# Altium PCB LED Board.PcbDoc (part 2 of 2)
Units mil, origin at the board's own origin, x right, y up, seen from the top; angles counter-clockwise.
Board outline 11968.5 x 3779.53 mil, 2 copper layers (Top Layer, Bottom Layer); 272 components, 796 nets, 779 pads, 57 vias.
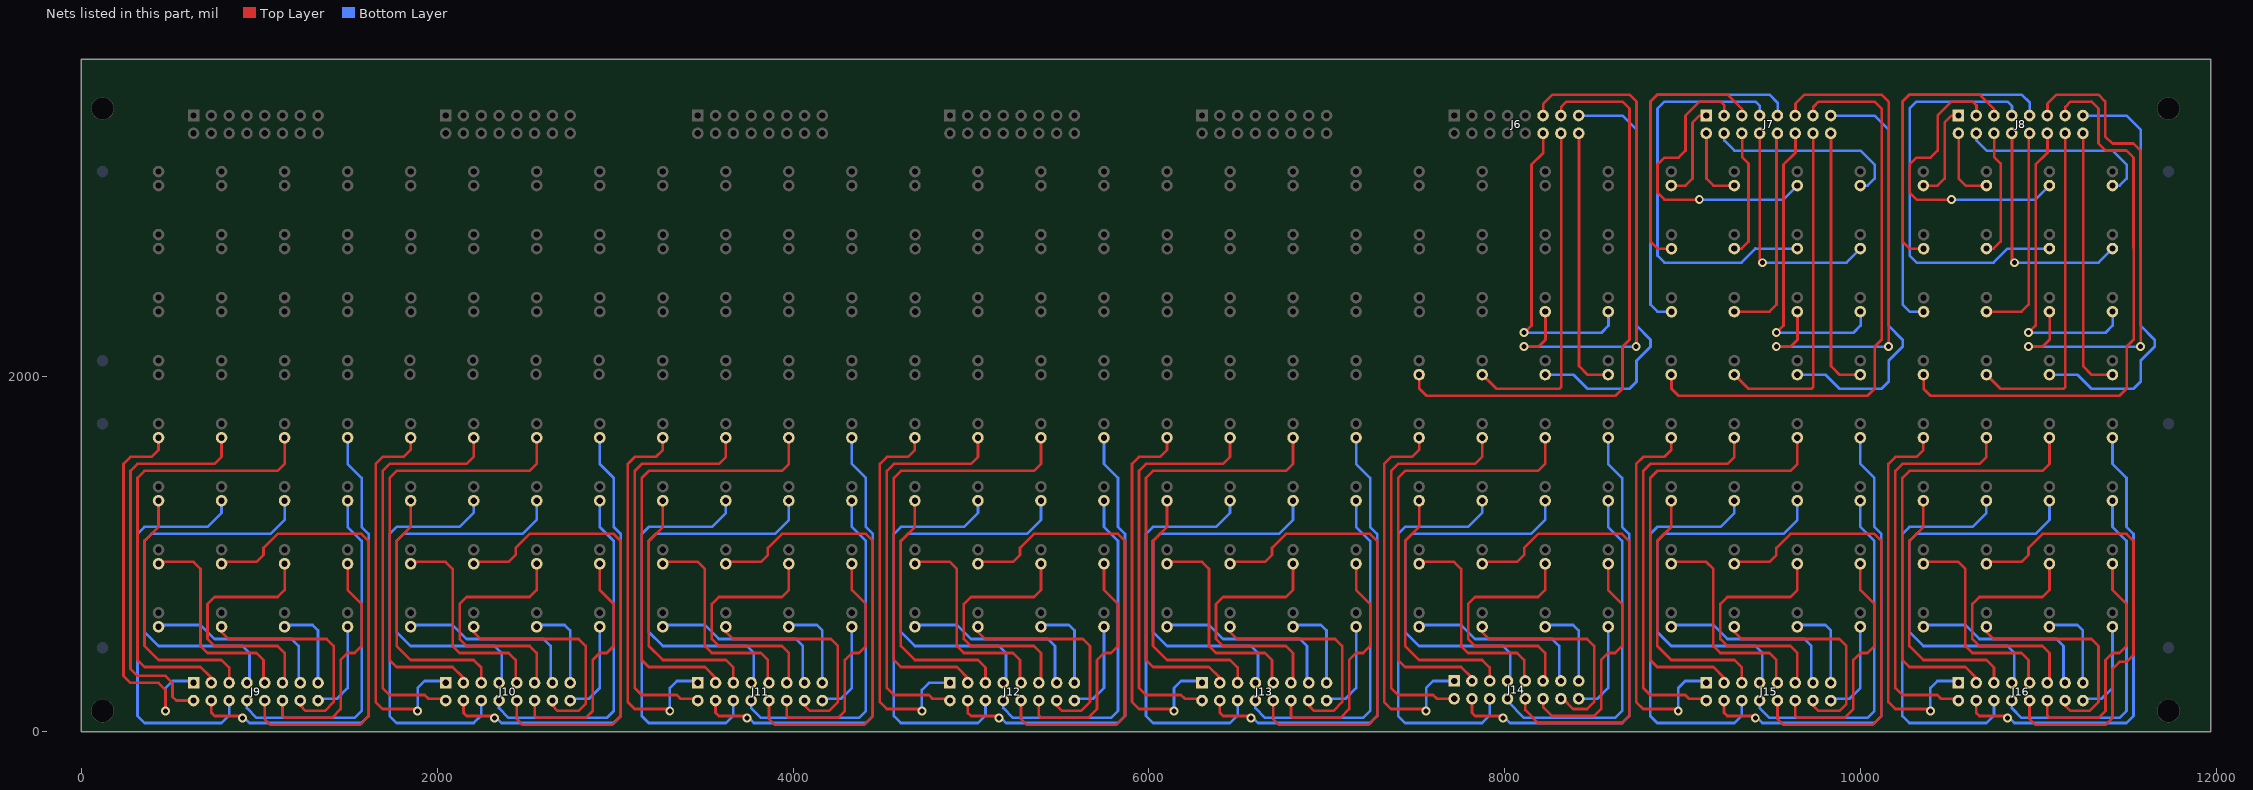
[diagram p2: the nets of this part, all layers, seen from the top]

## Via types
v1: diameter 50, hole 28, Top Layer to Bottom Layer, 57 vias

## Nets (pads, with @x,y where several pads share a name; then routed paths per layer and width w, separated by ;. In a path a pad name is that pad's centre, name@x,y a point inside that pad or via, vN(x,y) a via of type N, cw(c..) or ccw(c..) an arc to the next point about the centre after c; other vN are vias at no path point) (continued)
A91: D91.2 J6.11 | length 2927.8
  Top Layer w15: v1@8111.65,2164.72 8190.39,2164.72 8229.76,2204.09 D91.2@8229.76,2361.57 ; J6.11@8217.95,3463.94 8217.95,3530.86 8269.13,3582.05 8702.2,3582.05 8741.57,3542.68 v1@8741.57,2164.72
  Bottom Layer w15: v1@8111.65,2164.72 v1@8741.57,2164.72
  other v1: 8110.24,2165.35 8740.16,2165.35
A92: D92.2 J6.12 | length 1732
  Top Layer w15: v1@8111.65,2243.46 8151.02,2282.83 8151.02,3188.35 8217.95,3255.27 J6.12@8217.95,3363.94
  Bottom Layer w15: v1@8111.65,2243.46 8544.72,2243.46 8584.09,2282.83 D92.2@8584.09,2361.57
  other v1: 8110.24,2244.09
A93: D93.2 J6.13 | length 3306
  Top Layer w15: D93.2@7521.1,2007.24 7521.1,1928.5 7560.47,1889.13 8623.46,1889.13 8662.83,1928.5 8662.83,2164.72 8702.2,2204.09 8702.2,3503.31 8662.83,3542.68 8347.87,3542.68 8317.95,3512.75 J6.13@8317.95,3463.94
A94: D94.2 J6.14 | length 1905
  Top Layer w15: D94.2@7875.43,2007.24 7954.17,1928.5 8308.5,1928.5 8317.95,1937.95 J6.14@8317.95,3363.94
A95: D95.2 J6.15 | length 2399.5
  Bottom Layer w15: D95.2@8229.76,2007.24 8387.24,2007.24 8465.98,1928.5 8702.2,1928.5 8741.57,1967.87 8741.57,2085.98 8820.31,2164.72 8820.31,2204.09 8741.57,2282.83 8741.57,3385.2 8662.83,3463.94 J6.15@8417.95,3463.94
A96: D96.2 J6.16 | length 1494.7
  Top Layer w15: J6.16@8417.95,3363.94 8417.95,2055.28 8465.98,2007.24 D96.2@8584.09,2007.24
A97: D97.2 J7.1 | length 544.4
  Top Layer w15: D97.2@8938.42,3070.24 9017.17,3070.24 9056.54,3109.61 9056.54,3424.57 9095.9,3463.94 J7.1@9135.27,3463.94
A98: D98.2 J7.2 | length 428.1
  Top Layer w15: J7.2@9135.27,3363.94 9135.27,3109.61 9174.65,3070.24 D98.2@9292.76,3070.24
A99: D99.2 J7.3 | length 1697.8
  Top Layer w15: v1@9095.91,2991.5 8899.06,2991.5 8859.68,3030.87 8859.68,3188.35 8899.06,3227.72 8977.8,3227.72 9017.17,3267.09 9017.17,3463.94 9095.91,3542.68 9214.02,3542.68 9235.27,3521.42 J7.3@9235.27,3463.94
  Bottom Layer w15: v1@9095.91,2991.5 9568.35,2991.5 D99.2@9647.09,3070.24
  other v1: 9094.49,2992.13
A100: D100.2 J7.4 | length 1114.5
  Bottom Layer w15: J7.4@9235.27,3363.94 9235.27,3324.57 9292.76,3267.09 10001.42,3267.09 10080.16,3188.35 10080.16,3109.61 10040.79,3070.24 D100.2@10001.42,3070.24
A101: D101.2 J7.5 | length 1523.2
  Top Layer w15: D101.2@8938.43,2715.91 8859.69,2715.91 8820.31,2755.28 8820.31,3542.68 8859.68,3582.05 9253.39,3582.05 9335.27,3500.16 J7.5@9335.27,3463.94
A102: D102.2 J7.6 | length 718.7
  Top Layer w15: D102.2@9292.76,2715.91 9332.13,2715.91 9371.5,2755.28 9371.5,3194.64 9335.27,3230.86 J7.6@9335.27,3363.94
A103: D103.2 J7.7 | length 2319.4
  Bottom Layer w15: 9330.71,2637.8 9409.45,2716.54 ; 9332.13,2637.17 8899.06,2637.17 8859.68,2676.54 8859.68,3503.31 8899.06,3542.68 9410.87,3542.68 9435.27,3518.27 J7.7@9435.27,3463.94 ; 9410.87,2715.91 D103.2@9647.09,2715.91
A104: D104.2 J7.8 | length 1316.8
  Top Layer w15: J7.8@9435.27,3363.94 9435.27,2652.13 v1(9450.24,2637.17)
  Bottom Layer w15: v1(9450.24,2637.17) 9922.68,2637.17 D104.2@10001.42,2715.91
A105: D105.2 J7.9 | length 2098.8
  Bottom Layer w15: D105.2@8938.42,2361.58 8859.68,2361.57 8820.32,2400.94 8820.32,3542.68 8859.68,3582.05 9489.61,3582.05 9535.27,3536.38 J7.9@9535.27,3463.94
A106: D106.2 J7.10 | length 1218.1
  Top Layer w15: D106.2@9292.76,2361.57 9489.61,2361.57 9528.98,2400.94 9528.98,3357.64 J7.10@9535.27,3363.94
A107: D107.2 J7.11 | length 2927.8
  Top Layer w15: v1@9528.98,2164.72 9607.72,2164.72 9647.09,2204.09 D107.2@9647.09,2361.57 ; J7.11@9635.27,3463.94 9635.27,3530.86 9686.46,3582.05 10119.53,3582.05 10158.9,3542.68 v1@10158.9,2164.72
  Bottom Layer w15: v1@9528.98,2164.72 v1@10158.9,2164.72
  other v1: 9527.56,2165.35 10157.48,2165.35
A108: D108.2 J7.12 | length 1732
  Top Layer w15: v1@9528.98,2243.46 9568.35,2282.83 9568.35,3188.35 9635.27,3255.27 J7.12@9635.27,3363.94
  Bottom Layer w15: v1@9528.98,2243.46 9962.05,2243.46 10001.42,2282.83 D108.2@10001.42,2361.57
  other v1: 9527.56,2244.09
A109: D109.2 J7.13 | length 3306
  Top Layer w15: D109.2@8938.43,2007.24 8938.43,1928.5 8977.8,1889.13 10040.79,1889.13 10080.16,1928.5 10080.16,2164.72 10119.53,2204.09 10119.53,3503.31 10080.16,3542.68 9765.2,3542.68 9735.27,3512.75 J7.13@9735.27,3463.94
A110: D110.2 J7.14 | length 1905
  Top Layer w15: D110.2@9292.76,2007.24 9371.5,1928.5 9725.83,1928.5 9735.27,1937.95 J7.14@9735.27,3363.94
A111: D111.2 J7.15 | length 2399.5
  Bottom Layer w15: D111.2@9647.09,2007.24 9804.57,2007.24 9883.31,1928.5 10119.53,1928.5 10158.9,1967.87 10158.9,2085.98 10237.64,2164.72 10237.64,2204.09 10158.9,2282.83 10158.9,3385.2 10080.16,3463.94 J7.15@9835.27,3463.94
A112: D112.2 J7.16 | length 1494.7
  Top Layer w15: J7.16@9835.27,3363.94 9835.27,2055.28 9883.31,2007.24 D112.2@10001.42,2007.24
A113: D113.2 J8.1 | length 544.4
  Top Layer w15: D113.2@10355.75,3070.24 10434.49,3070.24 10473.86,3109.61 10473.86,3424.57 10513.23,3463.94 J8.1@10552.6,3463.94
A114: D114.2 J8.2 | length 428.1
  Top Layer w15: J8.2@10552.6,3363.94 10552.6,3109.61 10591.97,3070.24 D114.2@10710.08,3070.24
A115: D115.2 J8.3 | length 1697.8
  Top Layer w15: v1@10513.23,2991.5 10316.38,2991.5 10277.01,3030.87 10277.01,3188.35 10316.38,3227.72 10395.12,3227.72 10434.49,3267.09 10434.49,3463.94 10513.23,3542.68 10631.34,3542.68 10652.6,3521.42 J8.3@10652.6,3463.94
  Bottom Layer w15: v1@10513.23,2991.5 10985.67,2991.5 D115.2@11064.41,3070.24
  other v1: 10511.81,2992.13
A116: D116.2 J8.4 | length 1114.5
  Bottom Layer w15: J8.4@10652.6,3363.94 10652.6,3324.57 10710.08,3267.09 11418.74,3267.09 11497.48,3188.35 11497.48,3109.61 11458.11,3070.24 D116.2@11418.74,3070.24
A117: D117.2 J8.5 | length 1523.2
  Top Layer w15: D117.2@10355.75,2715.91 10277.01,2715.91 10237.64,2755.28 10237.64,3542.68 10277.01,3582.05 10670.71,3582.05 10752.6,3500.16 J8.5@10752.6,3463.94
A118: D118.2 J8.6 | length 718.7
  Top Layer w15: D118.2@10710.08,2715.91 10749.45,2715.91 10788.82,2755.28 10788.82,3194.64 10752.6,3230.86 J8.6@10752.6,3363.94
A119: D119.2 J8.7 | length 2319.4
  Bottom Layer w15: J8.7@10852.6,3463.94 10852.6,3518.27 10828.19,3542.68 10316.38,3542.68 10277.01,3503.31 10277.01,2676.54 10316.38,2637.17 10749.45,2637.17 10828.19,2715.91 D119.2@11064.41,2715.91
A120: D120.2 J8.8 | length 1316.8
  Top Layer w15: J8.8@10852.6,3363.94 10852.6,2652.13 v1(10867.56,2637.17)
  Bottom Layer w15: v1(10867.56,2637.17) 11340,2637.17 D120.2@11418.74,2715.91
A121: D121.2 J8.9 | length 2098.8
  Bottom Layer w15: D121.2@10355.75,2361.58 10277.01,2361.57 10237.64,2400.94 10237.64,3542.68 10277.01,3582.05 10906.93,3582.05 10952.6,3536.38 J8.9@10952.6,3463.94
A122: D122.2 J8.10 | length 1218.1
  Top Layer w15: D122.2@10710.08,2361.57 10906.93,2361.57 10946.3,2400.94 10946.3,3357.64 J8.10@10952.6,3363.94
A123: D123.2 J8.11 | length 2879.9
  Top Layer w15: v1@10946.3,2164.72 11025.04,2164.72 11064.41,2204.09 D123.2@11064.41,2361.57 ; J8.11@11052.6,3463.94 11052.6,3530.86 11103.78,3582.05 11337.95,3582.05 11376.69,3543.31 11376.69,3347.72 11417.32,3307.09 11535.43,3307.09 11574.8,3267.72 11576.22,2165.36 v1@11576.22,2164.72
  Bottom Layer w15: v1@10946.3,2164.72 v1@11576.22,2164.72
  other v1: 10944.88,2165.35 11574.8,2165.35
A124: D124.2 J8.12 | length 1732
  Top Layer w15: v1@10946.3,2243.46 10985.67,2282.83 10985.67,3188.35 11052.6,3255.27 J8.12@11052.6,3363.94
  Bottom Layer w15: v1@10946.3,2243.46 11379.37,2243.46 11418.74,2282.83 D124.2@11418.74,2361.57
  other v1: 10944.88,2244.09
A125: D125.2 J8.13 | length 3259.1
  Top Layer w15: D125.2@10355.75,2007.24 10355.75,1928.5 10395.12,1889.13 11458.11,1889.13 11497.48,1928.5 11497.48,2164.72 11536.85,2204.09 11535.43,3228.35 11496.06,3267.72 11377.95,3267.72 11338.58,3307.09 11338.58,3503.94 11299.21,3543.31 11182.52,3542.68 11152.6,3512.75 J8.13@11152.6,3463.94
A126: D126.2 J8.14 | length 1905
  Top Layer w15: D126.2@10710.08,2007.24 10788.82,1928.5 11143.15,1928.5 11152.6,1937.95 J8.14@11152.6,3363.94
A127: D127.2 J8.15 | length 2399.5
  Bottom Layer w15: D127.2@11064.41,2007.24 11221.89,2007.24 11300.63,1928.5 11536.85,1928.5 11576.22,1967.87 11576.22,2085.98 11654.96,2164.72 11654.96,2204.09 11576.22,2282.83 11576.22,3385.2 11497.48,3463.94 J8.15@11252.6,3463.94
A128: D128.2 J8.16 | length 1494.7
  Top Layer w15: J8.16@11252.6,3363.94 11252.6,2055.28 11300.63,2007.24 D128.2@11418.74,2007.24
A129: D129.2 J9.1 | length 2168.2
  Top Layer w15: D129.2@433.07,1663.78 433.07,1585.04 393.7,1545.67 275.59,1545.67 236.22,1506.3 236.22,314.96 275.59,275.59 433.07,275.59 472.44,236.22 v1@472.44,128.35
  Bottom Layer w15: v1@472.44,128.35 472.44,246.46 511.81,285.83 J9.1@629.92,285.83
  other v1: 472.44,118.11
A130: D130.2 J9.2 | length 2249.6
  Top Layer w15: J9.2@629.92,175.59 533.07,175.59 511.81,196.85 511.81,275.59 472.44,314.96 314.96,314.96 275.59,354.33 275.59,1466.93 314.96,1506.3 748.03,1506.3 787.4,1545.67 D130.2@787.4,1663.78
A131: D131.2 J9.3 | length 2496.9
  Top Layer w15: J9.3@729.92,303.94 669.29,364.57 354.33,364.57 314.96,403.94 314.96,1427.56 354.33,1466.93 1102.36,1466.93 1141.73,1506.3 D131.2@1141.73,1663.78
A132: D132.2 J9.4 | length 2626.8
  Top Layer w15: J9.4@729.92,185.83 729.92,107.09 748.03,88.98 v1@905.51,88.98
  Bottom Layer w15: v1@905.51,88.98 944.88,49.61 1574.8,49.61 1614.17,88.98 1614.17,1112.6 1574.8,1151.97 1574.8,1427.56 1496.06,1506.3 D132.2@1496.06,1663.78
  other v1: 905.51,78.74
A133: D133.2 J9.5 | length 1460.8
  Top Layer w15: D133.2@433.07,1309.45 433.07,1151.97 354.33,1073.23 354.33,482.68 433.07,403.94 787.4,403.94 829.92,361.42 J9.5@829.92,285.83
A134: D134.2 J9.6 | length 2266.3
  Bottom Layer w15: D134.2@787.4,1309.45 787.4,1230.71 708.66,1151.97 354.33,1151.97 314.96,1112.6 314.96,88.98 354.33,49.61 787.4,49.61 829.92,92.13 J9.6@829.92,185.83
A135: D135.2 J9.7 | length 2269.4
  Bottom Layer w15: J9.7@929.92,285.83 944.88,300.79 944.88,443.31 905.51,482.68 433.07,482.68 354.33,561.42 354.33,1073.23 393.7,1112.6 1062.99,1112.6 1141.73,1191.34 D135.2@1141.73,1309.45
A136: D136.2 J9.8 | length 1953.3
  Bottom Layer w15: J9.8@929.92,175.59 929.92,133.07 984.25,78.74 1535.43,78.74 1574.8,118.11 1574.8,1073.23 1496.06,1151.97 D136.2@1496.06,1309.45 ; J9.8@929.92,182.68 J9.8@929.92,185.83
A137: D137.2 J9.9 | length 1193.3
  Top Layer w15: D137.2@433.07,955.12 629.92,955.12 669.29,915.75 669.29,482.68 708.66,443.31 984.25,443.31 1023.62,403.94 1023.62,292.13 J9.9@1029.92,285.83
A138: D138.2 J9.10 | length 2647.5
  Top Layer w15: D138.2@787.4,955.12 984.25,955.12 1023.62,994.49 1023.62,1033.86 1102.36,1112.6 1574.8,1112.6 1614.17,1073.23 1614.17,88.98 1564.57,39.37 1062.99,39.37 1029.92,72.44 J9.10@1029.92,185.83
A139: D139.2 J9.11 | length 1448.1
  Top Layer w15: J9.11@1129.92,285.83 1141.73,297.64 1141.73,443.31 1102.36,482.68 748.03,482.68 708.66,522.05 708.66,718.9 748.03,758.27 1102.36,758.27 1141.73,797.64 D139.2@1141.73,955.12
A140: D140.2 J9.12 | length 1378.9
  Top Layer w15: J9.12@1129.92,185.83 1129.92,90.55 1141.73,78.74 1407.09,78.74 1456.69,128.35 1456.69,403.94 1496.06,443.31 1535.43,443.31 1574.8,482.68 1574.8,718.9 1496.06,797.64 D140.2@1496.06,955.12
A141: D141.2 J9.13 | length 1037.1
  Bottom Layer w15: D141.2@433.07,600.79 669.29,600.79 748.03,522.05 1181.1,522.05 1220.47,482.68 1220.47,295.28 J9.13@1229.92,285.83
A142: D142.2 J9.14 | length 1276.6
  Top Layer w15: D142.2@787.4,600.79 787.4,561.42 826.77,522.05 1377.95,522.05 1417.32,482.68 1417.32,167.72 1367.72,118.11 1259.84,118.11 1229.92,148.03 J9.14@1229.92,175.59 ; J9.14@1229.92,185.83 J9.14@1241.73,185.83
A143: D143.2 J9.15 | length 485.2
  Bottom Layer w15: D143.2@1141.73,600.79 1299.21,600.79 1329.92,570.08 J9.15@1329.92,285.83
A144: D144.2 J9.16 | length 545.6
  Bottom Layer w15: J9.16@1329.92,185.83 1435.43,185.83 1496.06,246.46 D144.2@1496.06,600.79
A145: D145.2 J10.1 | length 2191.2
  Top Layer w15: D145.2@1850.39,1663.78 1850.39,1585.04 1811.02,1545.67 1692.91,1545.67 1653.54,1506.3 1653.54,167.72 1692.91,128.35 v1@1889.76,128.35
  Bottom Layer w15: v1@1889.76,128.35 1889.76,246.46 1929.13,285.83 J10.1@2047.24,285.83
  other v1: 1889.76,118.11
A146: D146.2 J10.2 | length 2262.5
  Top Layer w15: J10.2@2047.24,185.83 1950.39,185.83 1929.13,207.09 1732.28,207.09 1692.91,246.46 1692.91,1466.93 1732.28,1506.3 2165.35,1506.3 2204.72,1545.67 D146.2@2204.72,1663.78
A147: D147.2 J10.3 | length 2496.9
  Top Layer w15: J10.3@2147.24,303.94 2086.61,364.57 1771.65,364.57 1732.28,403.94 1732.28,1427.56 1771.65,1466.93 2519.68,1466.93 2559.05,1506.3 D147.2@2559.05,1663.78
A148: D148.2 J10.4 | length 2626.8
  Top Layer w15: J10.4@2147.24,185.83 2147.24,107.09 2165.35,88.98 v1@2322.83,88.98
  Bottom Layer w15: v1@2322.83,88.98 2362.2,49.61 2992.12,49.61 3031.49,88.98 3031.49,1112.6 2992.12,1151.97 2992.12,1427.56 2913.39,1506.3 D148.2@2913.39,1663.78
  other v1: 2322.83,78.74
A149: D149.2 J10.5 | length 1460.8
  Top Layer w15: D149.2@1850.39,1309.45 1850.39,1151.97 1771.65,1073.23 1771.65,482.68 1850.39,403.94 2204.72,403.94 2247.24,361.42 J10.5@2247.24,285.83
A150: D150.2 J10.6 | length 2266.3
  Bottom Layer w15: D150.2@2204.72,1309.45 2204.72,1230.71 2125.98,1151.97 1771.65,1151.97 1732.28,1112.6 1732.28,88.98 1771.65,49.61 2204.72,49.61 2247.24,92.13 J10.6@2247.24,185.83
A151: D151.2 J10.7 | length 2269.4
  Bottom Layer w15: J10.7@2347.24,285.83 2362.2,300.79 2362.2,443.31 2322.83,482.68 1850.39,482.68 1771.65,561.42 1771.65,1073.23 1811.02,1112.6 2480.31,1112.6 2559.05,1191.34 D151.2@2559.05,1309.45
A152: D152.2 J10.8 | length 1953.3
  Bottom Layer w15: J10.8@2347.24,175.59 2347.24,133.07 2401.57,78.74 2952.76,78.74 2992.13,118.11 2992.13,207.09 ; J10.8@2347.24,182.68 J10.8@2347.24,185.83 ; D152.2@2913.38,1309.45 2913.38,1151.97 2992.12,1073.23 2992.12,207.09
A153: D153.2 J10.9 | length 1193.3
  Top Layer w15: D153.2@1850.39,955.12 2047.24,955.12 2086.61,915.75 2086.61,482.68 2125.98,443.31 2401.57,443.31 2440.94,403.94 2440.94,292.13 J10.9@2447.24,285.83
A154: D154.2 J10.10 | length 2647.5
  Top Layer w15: D154.2@2204.72,955.12 2401.57,955.12 2440.94,994.49 2440.94,1033.86 2519.68,1112.6 2992.12,1112.6 3031.49,1073.23 3031.49,88.98 2981.89,39.37 2480.32,39.37 2447.24,72.44 J10.10@2447.24,185.83
A155: D155.2 J10.11 | length 1448.1
  Top Layer w15: J10.11@2547.24,285.83 2559.05,297.64 2559.05,443.31 2519.68,482.68 2165.35,482.68 2125.98,522.05 2125.98,718.9 2165.35,758.27 2519.68,758.27 2559.05,797.64 D155.2@2559.05,955.12
A156: D156.2 J10.12 | length 1374.6
  Top Layer w15: J10.12@2547.24,175.59 2547.24,90.55 2559.06,78.74 2834.65,78.74 2874.01,118.11 2874.01,403.94 2913.38,443.31 2952.75,443.31 2992.12,482.68 2992.12,718.9 2913.38,797.64 D156.2@2913.38,955.12
A157: D157.2 J10.13 | length 1037.1
  Bottom Layer w15: D157.2@1850.39,600.79 2086.61,600.79 2165.35,522.05 2598.42,522.05 2637.79,482.68 2637.79,295.28 J10.13@2647.24,285.83
A158: D158.2 J10.14 | length 1282.6
  Top Layer w15: D158.2@2204.72,600.79 2204.72,561.42 2244.09,522.05 2795.27,522.05 2834.64,482.68 2834.64,157.48 2795.28,118.11 2677.17,118.11 2647.24,148.03 J10.14@2647.24,175.59 ; J10.14@2647.24,185.83 J10.14@2659.05,185.83
A159: D159.2 J10.15 | length 485.2
  Bottom Layer w15: D159.2@2559.05,600.79 2716.53,600.79 2747.24,570.08 J10.15@2747.24,285.83
A160: D160.2 J10.16 | length 545.6
  Bottom Layer w15: J10.16@2747.24,185.83 2852.75,185.83 2913.38,246.46 D160.2@2913.38,600.79
A161: D161.2 J11.1 | length 2191.2
  Top Layer w15: D161.2@3267.72,1663.78 3267.72,1585.04 3228.34,1545.67 3110.23,1545.67 3070.86,1506.3 3070.86,167.72 3110.23,128.35 v1@3307.08,128.35
  Bottom Layer w15: v1@3307.08,128.35 3307.08,246.46 3346.45,285.83 J11.1@3464.56,285.83
  other v1: 3307.09,118.11
A162: D162.2 J11.2 | length 2262.5
  Top Layer w15: J11.2@3464.57,185.83 3367.71,185.83 3346.45,207.09 3149.6,207.09 3110.23,246.46 3110.23,1466.93 3149.6,1506.3 3582.67,1506.3 3622.05,1545.67 D162.2@3622.05,1663.78
A163: D163.2 J11.3 | length 2496.9
  Top Layer w15: J11.3@3564.57,303.94 3503.93,364.57 3188.97,364.57 3149.6,403.94 3149.6,1427.56 3188.97,1466.93 3937.01,1466.93 3976.38,1506.3 D163.2@3976.38,1663.78
A164: D164.2 J11.4 | length 2626.8
  Top Layer w15: J11.4@3564.57,185.83 3564.57,107.09 3582.67,88.98 v1@3740.15,88.98
  Bottom Layer w15: v1@3740.15,88.98 3779.52,49.61 4409.45,49.61 4448.82,88.98 4448.82,1112.6 4409.45,1151.97 4409.45,1427.56 4330.71,1506.3 D164.2@4330.71,1663.78
  other v1: 3740.16,78.74
A165: D165.2 J11.5 | length 1460.8
  Top Layer w15: D165.2@3267.71,1309.45 3267.71,1151.97 3188.97,1073.23 3188.97,482.68 3267.71,403.94 3622.04,403.94 3664.57,361.42 J11.5@3664.57,285.83
A166: D166.2 J11.6 | length 2266.3
  Bottom Layer w15: D166.2@3622.04,1309.45 3622.04,1230.71 3543.3,1151.97 3188.97,1151.97 3149.6,1112.6 3149.6,88.98 3188.97,49.61 3622.04,49.61 3664.57,92.13 J11.6@3664.57,185.83
A167: D167.2 J11.7 | length 2269.4
  Bottom Layer w15: J11.7@3764.57,285.83 3779.52,300.79 3779.52,443.31 3740.15,482.68 3267.71,482.68 3188.97,561.42 3188.97,1073.23 3228.34,1112.6 3897.64,1112.6 3976.38,1191.34 D167.2@3976.38,1309.45
A168: D168.2 J11.8 | length 1953.3
  Bottom Layer w15: J11.8@3764.57,175.59 3764.57,133.07 3818.9,78.74 4370.08,78.74 4409.45,118.11 4409.45,207.08 4409.45,1073.23 4330.71,1151.97 D168.2@4330.71,1309.45 ; J11.8@3764.57,182.68 J11.8@3764.57,185.83
A169: D169.2 J11.9 | length 1193.3
  Top Layer w15: D169.2@3267.72,955.12 3464.56,955.12 3503.93,915.75 3503.93,482.68 3543.3,443.31 3818.9,443.31 3858.27,403.94 3858.27,292.13 J11.9@3864.57,285.83
A170: D170.2 J11.10 | length 2647.5
  Top Layer w15: D170.2@3622.05,955.12 3818.9,955.12 3858.27,994.49 3858.27,1033.86 3937.01,1112.6 4409.45,1112.6 4448.82,1073.23 4448.82,88.98 4399.21,39.37 3897.64,39.37 3864.57,72.44 J11.10@3864.57,185.83
A171: D171.2 J11.11 | length 1448.1
  Top Layer w15: J11.11@3964.57,285.83 3976.38,297.64 3976.38,443.31 3937.01,482.68 3582.67,482.68 3543.3,522.05 3543.3,718.9 3582.67,758.27 3937.01,758.27 3976.38,797.64 D171.2@3976.38,955.12
A172: D172.2 J11.12 | length 1384.9
  Top Layer w15: J11.12@3964.57,185.83 3964.57,90.55 3976.38,78.74 4251.97,78.74 4291.34,118.11 4291.34,403.94 4330.71,443.31 4370.08,443.31 4409.45,482.68 4409.45,718.9 4330.71,797.64 D172.2@4330.71,955.12
A173: D173.2 J11.13 | length 1037.1
  Bottom Layer w15: D173.2@3267.71,600.79 3503.93,600.79 3582.67,522.05 4015.75,522.05 4055.12,482.68 4055.12,295.28 J11.13@4064.57,285.83
A174: D174.2 J11.14 | length 1276.6
  Top Layer w15: D174.2@3622.04,600.79 3622.04,561.42 3661.41,522.05 4212.6,522.05 4251.97,482.68 4251.97,167.72 4202.36,118.11 4094.49,118.11 4064.57,148.03 J11.14@4064.57,175.59 ; J11.14@4064.57,185.83 J11.14@4076.37,185.83
A175: D175.2 J11.15 | length 485.2
  Bottom Layer w15: D175.2@3976.38,600.79 4133.86,600.79 4164.57,570.08 J11.15@4164.57,285.83
A176: D176.2 J11.16 | length 545.6
  Bottom Layer w15: J11.16@4164.57,185.83 4270.08,185.83 4330.71,246.46 D176.2@4330.71,600.79
A177: D177.2 J12.1 | length 2191.2
  Top Layer w15: D177.2@4685.04,1663.78 4685.04,1585.04 4645.67,1545.67 4527.56,1545.67 4488.19,1506.3 4488.19,167.72 4527.56,128.35 v1@4724.41,128.35
  Bottom Layer w15: v1(4724.41,118.11) 4724.41,236.22 4763.78,275.59 J12.1@4881.89,275.59
A178: D178.2 J12.2 | length 2262.5
  Top Layer w15: J12.2@4881.89,185.83 4785.04,185.83 4763.78,207.09 4566.93,207.09 4527.56,246.46 4527.56,1466.93 4566.93,1506.3 5000,1506.3 5039.37,1545.67 D178.2@5039.37,1663.78
A179: D179.2 J12.3 | length 2496.9
  Top Layer w15: J12.3@4981.89,303.94 4921.26,364.57 4606.3,364.57 4566.93,403.94 4566.93,1427.56 4606.3,1466.93 5354.33,1466.93 5393.7,1506.3 D179.2@5393.7,1663.78
A180: D180.2 J12.4 | length 2626.8
  Top Layer w15: J12.4@4981.89,185.83 4981.89,107.09 5000,88.98 v1@5157.48,88.98
  Bottom Layer w15: v1@5157.48,88.98 5196.85,49.61 5826.77,49.61 5866.14,88.98 5866.14,1112.6 5826.77,1151.97 5826.77,1427.56 5748.03,1506.3 D180.2@5748.03,1663.78
  other v1: 5157.48,78.74
A181: D181.2 J12.5 | length 1460.8
  Top Layer w15: D181.2@4685.04,1309.45 4685.04,1151.97 4606.3,1073.23 4606.3,482.68 4685.04,403.94 5039.37,403.94 5081.89,361.42 J12.5@5081.89,285.83
A182: D182.2 J12.6 | length 2266.3
  Bottom Layer w15: D182.2@5039.37,1309.45 5039.37,1230.71 4960.63,1151.97 4606.3,1151.97 4566.93,1112.6 4566.93,88.98 4606.3,49.61 5039.37,49.61 5081.89,92.13 J12.6@5081.89,185.83
A183: D183.2 J12.7 | length 2269.4
  Bottom Layer w15: J12.7@5181.89,285.83 5196.85,300.79 5196.85,443.31 5157.48,482.68 4685.04,482.68 4606.3,561.42 4606.3,1073.23 4645.67,1112.6 5314.96,1112.6 5393.7,1191.34 D183.2@5393.7,1309.45
A184: D184.2 J12.8 | length 1953.3
  Bottom Layer w15: J12.8@5181.89,175.59 5181.89,133.07 5236.22,78.74 5787.4,78.74 5826.77,118.11 5826.77,1073.23 5748.03,1151.97 D184.2@5748.03,1309.45 ; J12.8@5181.89,182.68 J12.8@5181.89,185.83
A185: D185.2 J12.9 | length 1193.3
  Top Layer w15: D185.2@4685.04,955.12 4881.89,955.12 4921.26,915.75 4921.26,482.68 4960.63,443.31 5236.22,443.31 5275.59,403.94 5275.59,292.13 J12.9@5281.89,285.83
A186: D186.2 J12.10 | length 2647.5
  Top Layer w15: D186.2@5039.37,955.12 5236.22,955.12 5275.59,994.49 5275.59,1033.86 5354.33,1112.6 5826.77,1112.6 5866.14,1073.23 5866.14,88.98 5816.53,39.37 5314.96,39.37 5281.89,72.44 J12.10@5281.89,185.83
A187: D187.2 J12.11 | length 1448.1
  Top Layer w15: J12.11@5381.89,285.83 5393.7,297.64 5393.7,443.31 5354.33,482.68 5000,482.68 4960.63,522.05 4960.63,718.9 5000,758.27 5354.33,758.27 5393.7,797.64 D187.2@5393.7,955.12
A188: D188.2 J12.12 | length 1378.9
  Top Layer w15: J12.12@5381.89,185.83 5381.89,90.55 5393.7,78.74 5659.05,78.74 5708.66,128.35 5708.66,403.94 5748.03,443.31 5787.4,443.31 5826.77,482.68 5826.77,718.9 5748.03,797.64 D188.2@5748.03,955.12
A189: D189.2 J12.13 | length 1037.1
  Bottom Layer w15: D189.2@4685.04,600.79 4921.26,600.79 5000,522.05 5433.07,522.05 5472.44,482.68 5472.44,295.28 J12.13@5481.89,285.83
A190: D190.2 J12.14 | length 1276.6
  Top Layer w15: D190.2@5039.37,600.79 5039.37,561.42 5078.74,522.05 5629.92,522.05 5669.29,482.68 5669.29,167.72 5619.68,118.11 5511.81,118.11 5481.89,148.03 J12.14@5481.89,175.59 ; J12.14@5481.89,185.83 J12.14@5493.7,185.83
A191: D191.2 J12.15 | length 485.2
  Bottom Layer w15: D191.2@5393.7,600.79 5551.18,600.79 5581.89,570.08 J12.15@5581.89,285.83
A192: D192.2 J12.16 | length 545.6
  Bottom Layer w15: J12.16@5581.89,185.83 5687.4,185.83 5748.03,246.46 D192.2@5748.03,600.79
A193: D193.2 J13.1 | length 2191.2
  Top Layer w15: D193.2@6102.36,1663.78 6102.36,1585.04 6062.99,1545.67 5944.88,1545.67 5905.51,1506.3 5905.51,167.72 5944.88,128.35 v1@6141.73,128.35
  Bottom Layer w15: v1@6141.73,128.35 6141.73,246.46 6181.1,285.83 J13.1@6299.21,285.83
  other v1: 6141.73,118.11
A194: D194.2 J13.2 | length 2262.5
  Top Layer w15: J13.2@6299.21,185.83 6202.36,185.83 6181.1,207.09 5984.25,207.09 5944.88,246.46 5944.88,1466.93 5984.25,1506.3 6417.32,1506.3 6456.69,1545.67 D194.2@6456.69,1663.78
A195: D195.2 J13.3 | length 2496.9
  Top Layer w15: J13.3@6399.21,303.94 6338.58,364.57 6023.62,364.57 5984.25,403.94 5984.25,1427.56 6023.62,1466.93 6771.65,1466.93 6811.02,1506.3 D195.2@6811.02,1663.78
A196: D196.2 J13.4 | length 2626.8
  Top Layer w15: J13.4@6399.21,185.83 6399.21,107.09 6417.32,88.98 v1@6574.8,88.98
  Bottom Layer w15: v1@6574.8,88.98 6614.17,49.61 7244.09,49.61 7283.46,88.98 7283.46,1112.6 7244.09,1151.97 7244.09,1427.56 7165.35,1506.3 D196.2@7165.35,1663.78
  other v1: 6574.8,78.74
A197: D197.2 J13.5 | length 1460.8
  Top Layer w15: D197.2@6102.36,1309.45 6102.36,1151.97 6023.62,1073.23 6023.62,482.68 6102.36,403.94 6456.69,403.94 6499.21,361.42 J13.5@6499.21,285.83
A198: D198.2 J13.6 | length 2266.3
  Bottom Layer w15: D198.2@6456.69,1309.45 6456.69,1230.71 6377.95,1151.97 6023.62,1151.97 5984.25,1112.6 5984.25,88.98 6023.62,49.61 6456.69,49.61 6499.21,92.13 J13.6@6499.21,185.83
A199: D199.2 J13.7 | length 2269.4
  Bottom Layer w15: J13.7@6599.21,285.83 6614.17,300.79 6614.17,443.31 6574.8,482.68 6102.36,482.68 6023.62,561.42 6023.62,1073.23 6062.99,1112.6 6732.28,1112.6 6811.02,1191.34 D199.2@6811.02,1309.45
A200: D200.2 J13.8 | length 1953.3
  Bottom Layer w15: J13.8@6599.21,175.59 6599.21,133.07 6653.54,78.74 7204.72,78.74 7244.09,118.11 7244.09,207.08 7244.09,1073.23 7165.35,1151.97 D200.2@7165.35,1309.45 ; J13.8@6599.21,182.68 J13.8@6599.21,185.83
A201: D201.2 J13.9 | length 1193.3
  Top Layer w15: D201.2@6102.36,955.12 6299.21,955.12 6338.58,915.75 6338.58,482.68 6377.95,443.31 6653.54,443.31 6692.91,403.94 6692.91,292.13 J13.9@6699.21,285.83
A202: D202.2 J13.10 | length 2647.5
  Top Layer w15: D202.2@6456.69,955.12 6653.54,955.12 6692.91,994.49 6692.91,1033.86 6771.65,1112.6 7244.09,1112.6 7283.46,1073.23 7283.46,88.98 7233.86,39.37 6732.28,39.37 6699.21,72.44 J13.10@6699.21,185.83
A203: D203.2 J13.11 | length 1448.1
  Top Layer w15: J13.11@6799.21,285.83 6811.02,297.64 6811.02,443.31 6771.65,482.68 6417.32,482.68 6377.95,522.05 6377.95,718.9 6417.32,758.27 6771.65,758.27 6811.02,797.64 D203.2@6811.02,955.12
A204: D204.2 J13.12 | length 1378.9
  Top Layer w15: J13.12@6799.21,185.83 6799.21,90.55 6811.02,78.74 7076.38,78.74 7125.98,128.35 7125.98,403.94 7165.35,443.31 7204.72,443.31 7244.09,482.68 7244.09,718.9 7165.35,797.64 D204.2@7165.35,955.12
A205: D205.2 J13.13 | length 1037.1
  Bottom Layer w15: D205.2@6102.36,600.79 6338.58,600.79 6417.32,522.05 6850.39,522.05 6889.76,482.68 6889.76,295.28 J13.13@6899.21,285.83
A206: D206.2 J13.14 | length 1276.6
  Top Layer w15: D206.2@6456.69,600.79 6456.69,561.42 6496.06,522.05 7047.24,522.05 7086.61,482.68 7086.61,167.72 7037.01,118.11 6929.13,118.11 6899.21,148.03 J13.14@6899.21,175.59 ; J13.14@6899.21,185.83 J13.14@6911.02,185.83
A207: D207.2 J13.15 | length 485.2
  Bottom Layer w15: D207.2@6811.02,600.79 6968.5,600.79 6999.21,570.08 J13.15@6999.21,285.83
A208: D208.2 J13.16 | length 545.6
  Bottom Layer w15: J13.16@6999.21,185.83 7104.72,185.83 7165.35,246.46 D208.2@7165.35,600.79
A209: D209.2 J14.1 | length 2191.2
  Top Layer w15: D209.2@7519.69,1663.78 7519.69,1585.04 7480.31,1545.67 7362.2,1545.67 7322.83,1506.3 7322.83,167.72 7362.2,128.35 v1@7559.05,128.35
  Bottom Layer w15: v1@7559.05,128.35 7559.05,246.46 7598.42,285.83 J14.1@7716.53,285.83
  other v1: 7559.06,118.11
A210: D210.2 J14.2 | length 2262.5
  Top Layer w15: J14.2@7716.53,185.83 7619.68,185.83 7598.42,207.09 7401.57,207.09 7362.2,246.46 7362.2,1466.93 7401.57,1506.3 7834.64,1506.3 7874.02,1545.67 D210.2@7874.02,1663.78
A211: D211.2 J14.3 | length 2496.9
  Top Layer w15: J14.3@7816.54,303.94 7755.9,364.57 7440.94,364.57 7401.57,403.94 7401.57,1427.56 7440.94,1466.93 8188.98,1466.93 8228.35,1506.3 D211.2@8228.35,1663.78
A212: D212.2 J14.4 | length 2626.8
  Top Layer w15: J14.4@7816.53,185.83 7816.54,107.09 7834.64,88.98 v1@7992.13,88.98
  Bottom Layer w15: v1@7992.13,88.98 8031.5,49.61 8661.42,49.61 8700.79,88.98 8700.79,1112.6 8661.42,1151.97 8661.42,1427.56 8582.68,1506.3 D212.2@8582.68,1663.78
  other v1: 7992.13,78.74
A213: D213.2 J14.5 | length 1460.8
  Top Layer w15: D213.2@7519.68,1309.45 7519.68,1151.97 7440.94,1073.23 7440.94,482.68 7519.68,403.94 7874.01,403.94 7916.54,361.42 J14.5@7916.53,285.83
A214: D214.2 J14.6 | length 2266.3
  Bottom Layer w15: D214.2@7874.01,1309.45 7874.01,1230.71 7795.27,1151.97 7440.94,1151.97 7401.57,1112.6 7401.57,88.98 7440.94,49.61 7874.01,49.61 7916.54,92.13 J14.6@7916.53,185.83
A215: D215.2 J14.7 | length 2269.4
  Bottom Layer w15: J14.7@8016.53,285.83 8031.5,300.79 8031.5,443.31 7992.13,482.68 7519.68,482.68 7440.94,561.42 7440.94,1073.23 7480.31,1112.6 8149.61,1112.6 8228.35,1191.34 D215.2@8228.35,1309.45
A216: D216.2 J14.8 | length 1930.3
  Bottom Layer w15: J14.8@8016.53,175.59 8016.53,172.44 8110.24,78.74 8622.05,78.74 8661.42,118.11 8661.42,207.09 8661.42,1073.23 8582.68,1151.97 D216.2@8582.68,1309.45 ; J14.8@8016.54,182.68 J14.8@8016.53,185.83
A217: D217.2 J14.9 | length 1193.3
  Top Layer w15: D217.2@7519.69,955.12 7716.53,955.12 7755.9,915.75 7755.9,482.68 7795.27,443.31 8070.87,443.31 8110.24,403.94 8110.24,292.13 J14.9@8116.53,285.83
A218: D218.2 J14.10 | length 2610
  Top Layer w15: D218.2@7874.02,955.12 8070.87,955.12 8110.24,994.49 8110.24,1033.86 8188.98,1112.6 8661.42,1112.6 8700.79,1073.23 8700.79,88.98 8661.42,49.61 8188.98,49.61 8116.54,122.05 J14.10@8116.53,185.83
A219: D219.2 J14.11 | length 1448.1
  Top Layer w15: J14.11@8216.53,285.83 8228.35,297.64 8228.35,443.31 8188.98,482.68 7834.64,482.68 7795.27,522.05 7795.27,718.9 7834.64,758.27 8188.98,758.27 8228.35,797.64 D219.2@8228.35,955.12
A220: D220.2 J14.12 | length 1341.3
  Top Layer w15: J14.12@8216.53,185.83 8216.54,140.16 8267.72,88.98 8503.94,88.98 8543.31,128.35 8543.31,403.94 8582.68,443.31 8622.05,443.31 8661.42,482.68 8661.42,718.9 8582.68,797.64 D220.2@8582.68,955.12
A221: D221.2 J14.13 | length 1037.1
  Bottom Layer w15: D221.2@7519.68,600.79 7755.9,600.79 7834.64,522.05 8267.72,522.05 8307.09,482.68 8307.09,295.28 J14.13@8316.53,285.83
A222: D222.2 J14.14 | length 1244.4
  Top Layer w15: D222.2@7874.01,600.79 7874.01,561.42 7913.39,522.05 8464.57,522.05 8503.94,482.68 8503.94,167.72 8464.57,128.35 8385.83,128.35 8328.34,185.83 J14.14@8316.53,185.83
A223: D223.2 J14.15 | length 485.2
  Bottom Layer w15: D223.2@8228.35,600.79 8385.83,600.79 8416.54,570.08 J14.15@8416.53,285.83
A224: D224.2 J14.16 | length 545.6
  Bottom Layer w15: J14.16@8416.53,185.83 8522.05,185.83 8582.68,246.46 D224.2@8582.68,600.79
A225: D225.2 J15.1 | length 2191.2
  Top Layer w15: D225.2@8937.01,1663.78 8937.01,1585.04 8897.64,1545.67 8779.53,1545.67 8740.16,1506.3 8740.16,167.72 8779.53,128.35 v1@8976.38,128.35
  Bottom Layer w15: v1@8976.38,128.35 8976.38,246.46 9015.75,285.83 J15.1@9133.86,285.83
  other v1: 8976.38,118.11
A226: D226.2 J15.2 | length 2262.5
  Top Layer w15: J15.2@9133.86,185.83 9037.01,185.83 9015.75,207.09 8818.9,207.09 8779.53,246.46 8779.53,1466.93 8818.9,1506.3 9251.97,1506.3 9291.34,1545.67 D226.2@9291.34,1663.78
A227: D227.2 J15.3 | length 2496.9
  Top Layer w15: J15.3@9233.86,303.94 9173.23,364.57 8858.27,364.57 8818.9,403.94 8818.9,1427.56 8858.27,1466.93 9606.3,1466.93 9645.67,1506.3 D227.2@9645.67,1663.78
A228: D228.2 J15.4 | length 2626.8
  Top Layer w15: J15.4@9233.86,185.83 9233.86,107.09 9251.97,88.98 v1@9409.45,88.98
  Bottom Layer w15: v1@9409.45,88.98 9448.82,49.61 10078.74,49.61 10118.11,88.98 10118.11,1112.6 10078.74,1151.97 10078.74,1427.56 10000,1506.3 D228.2@10000,1663.78
  other v1: 9409.45,78.74
A229: D229.2 J15.5 | length 1460.8
  Top Layer w15: D229.2@8937.01,1309.45 8937.01,1151.97 8858.27,1073.23 8858.27,482.68 8937.01,403.94 9291.34,403.94 9333.86,361.42 J15.5@9333.86,285.83
A230: D230.2 J15.6 | length 2266.3
  Bottom Layer w15: D230.2@9291.34,1309.45 9291.34,1230.71 9212.6,1151.97 8858.27,1151.97 8818.9,1112.6 8818.9,88.98 8858.27,49.61 9291.34,49.61 9333.86,92.13 J15.6@9333.86,185.83
A231: D231.2 J15.7 | length 2269.4
  Bottom Layer w15: J15.7@9433.86,285.83 9448.82,300.79 9448.82,443.31 9409.45,482.68 8937.01,482.68 8858.27,561.42 8858.27,1073.23 8897.64,1112.6 9566.93,1112.6 9645.67,1191.34 D231.2@9645.67,1309.45
A232: D232.2 J15.8 | length 1953.3
  Bottom Layer w15: J15.8@9433.86,175.59 9433.86,133.07 9488.19,78.74 10039.37,78.74 10078.74,118.11 10078.74,207.09 10078.74,1073.23 10000,1151.97 D232.2@10000,1309.45 ; J15.8@9433.86,182.68 J15.8@9433.86,185.83
A233: D233.2 J15.9 | length 1193.3
  Top Layer w15: D233.2@8937.01,955.12 9133.86,955.12 9173.23,915.75 9173.23,482.68 9212.6,443.31 9488.19,443.31 9527.56,403.94 9527.56,292.13 J15.9@9533.86,285.83
A234: D234.2 J15.10 | length 2647.5
  Top Layer w15: D234.2@9291.34,955.12 9488.19,955.12 9527.56,994.49 9527.56,1033.86 9606.3,1112.6 10078.74,1112.6 10118.11,1073.23 10118.11,88.98 10068.5,39.37 9566.93,39.37 9533.86,72.44 J15.10@9533.86,185.83
A235: D235.2 J15.11 | length 1448.1
  Top Layer w15: J15.11@9633.86,285.83 9645.67,297.64 9645.67,443.31 9606.3,482.68 9251.97,482.68 9212.6,522.05 9212.6,718.9 9251.97,758.27 9606.3,758.27 9645.67,797.64 D235.2@9645.67,955.12
A236: D236.2 J15.12 | length 1378.9
  Top Layer w15: J15.12@9633.86,185.83 9633.86,90.55 9645.67,78.74 9911.02,78.74 9960.63,128.35 9960.63,403.94 10000,443.31 10039.37,443.31 10078.74,482.68 10078.74,718.9 10000,797.64 D236.2@10000,955.12
A237: D237.2 J15.13 | length 1037.1
  Bottom Layer w15: D237.2@8937.01,600.79 9173.23,600.79 9251.97,522.05 9685.04,522.05 9724.41,482.68 9724.41,295.28 J15.13@9733.86,285.83
A238: D238.2 J15.14 | length 1270.8
  Top Layer w15: D238.2@9291.34,600.79 9291.34,561.42 9330.71,522.05 9881.89,522.05 9921.26,482.68 9921.26,157.48 9881.89,118.11 9763.78,118.11 9733.86,148.03 J15.14@9733.86,175.59
A239: D239.2 J15.15 | length 485.2
  Bottom Layer w15: D239.2@9645.67,600.79 9803.15,600.79 9833.86,570.08 J15.15@9833.86,285.83
A240: D240.2 J15.16 | length 545.6
  Bottom Layer w15: J15.16@9833.86,185.83 9939.37,185.83 10000,246.46 D240.2@10000,600.79
A241: D241.2 J16.1 | length 2191.2
  Top Layer w15: D241.2@10354.33,1663.78 10354.33,1585.04 10314.96,1545.67 10196.85,1545.67 10157.48,1506.3 10157.48,167.72 10196.85,128.35 v1@10393.7,128.35
  Bottom Layer w15: v1@10393.7,128.35 10393.7,246.46 10433.07,285.83 J16.1@10551.18,285.83
  other v1: 10393.7,118.11
A242: D242.2 J16.2 | length 2262.5
  Top Layer w15: J16.2@10551.18,185.83 10454.33,185.83 10433.07,207.09 10236.22,207.09 10196.85,246.46 10196.85,1466.93 10236.22,1506.3 10669.29,1506.3 10708.66,1545.67 D242.2@10708.66,1663.78
A243: D243.2 J16.3 | length 2496.9
  Top Layer w15: J16.3@10651.18,303.94 10590.55,364.57 10275.59,364.57 10236.22,403.94 10236.22,1427.56 10275.59,1466.93 11023.62,1466.93 11062.99,1506.3 D243.2@11062.99,1663.78
A244: D244.2 J16.4 | length 2626.8
  Top Layer w15: J16.4@10651.18,185.83 10651.18,107.09 10669.29,88.98 v1@10826.77,88.98
  Bottom Layer w15: v1@10826.77,88.98 10866.14,49.61 11496.06,49.61 11535.43,88.98 11535.43,1112.6 11496.06,1151.97 11496.06,1427.56 11417.32,1506.3 D244.2@11417.32,1663.78
  other v1: 10826.77,78.74
A245: D245.2 J16.5 | length 1460.8
  Top Layer w15: D245.2@10354.33,1309.45 10354.33,1151.97 10275.59,1073.23 10275.59,482.68 10354.33,403.94 10708.66,403.94 10751.18,361.42 J16.5@10751.18,285.83
A246: D246.2 J16.6 | length 2266.3
  Bottom Layer w15: D246.2@10708.66,1309.45 10708.66,1230.71 10629.92,1151.97 10275.59,1151.97 10236.22,1112.6 10236.22,88.98 10275.59,49.61 10708.66,49.61 10751.18,92.13 J16.6@10751.18,185.83
A247: D247.2 J16.7 | length 2269.4
  Bottom Layer w15: J16.7@10851.18,285.83 10866.14,300.79 10866.14,443.31 10826.77,482.68 10354.33,482.68 10275.59,561.42 10275.59,1073.23 10314.96,1112.6 10984.25,1112.6 11062.99,1191.34 D247.2@11062.99,1309.45
A248: D248.2 J16.8 | length 1953.3
  Bottom Layer w15: J16.8@10851.18,175.59 10851.18,133.07 10905.51,78.74 11456.69,78.74 11496.06,118.11 11496.06,207.09 11496.06,1073.23 11417.32,1151.97 D248.2@11417.32,1309.45 ; J16.8@10851.18,182.68 J16.8@10851.18,185.83
A249: D249.2 J16.9 | length 1193.3
  Top Layer w15: D249.2@10354.33,955.12 10551.18,955.12 10590.55,915.75 10590.55,482.68 10629.92,443.31 10905.51,443.31 10944.88,403.94 10944.88,292.13 J16.9@10951.18,285.83
A250: D250.2 J16.10 | length 2607.4
  Top Layer w15: D250.2@10708.66,955.12 10905.51,955.12 10944.88,994.49 10944.88,1033.86 11023.62,1112.6 11496.06,1112.6 11535.43,1073.23 11535.43,433.07 11496.06,393.7 11456.69,393.7 11417.32,354.33 11417.32,78.74 11377.95,39.37 10984.25,39.37 10951.18,72.44 J16.10@10951.18,185.83
A251: D251.2 J16.11 | length 1448.1
  Top Layer w15: J16.11@11051.18,285.83 11062.99,297.64 11062.99,443.31 11023.62,482.68 10669.29,482.68 10629.92,522.05 10629.92,718.9 10669.29,758.27 11023.62,758.27 11062.99,797.64 D251.2@11062.99,955.12
A252: D252.2 J16.12 | length 1384.9
  Top Layer w15: J16.12@11051.18,185.83 11051.18,90.55 11062.99,78.74 11338.58,78.74 11377.95,118.11 11377.95,403.94 11417.32,443.31 11456.69,443.31 11496.06,482.68 11496.06,718.9 11417.32,797.64 D252.2@11417.32,955.12
A253: D253.2 J16.13 | length 1037.1
  Bottom Layer w15: D253.2@10354.33,600.79 10590.55,600.79 10669.29,522.05 11102.36,522.05 11141.73,482.68 11141.73,295.28 J16.13@11151.18,285.83
A254: D254.2 J16.14 | length 1276.6
  Top Layer w15: D254.2@10708.66,600.79 10708.66,561.42 10748.03,522.05 11299.21,522.05 11338.58,482.68 11338.58,167.72 11288.98,118.11 11181.1,118.11 11151.18,148.03 J16.14@11151.18,175.59 ; J16.14@11151.18,185.83 J16.14@11162.99,185.83
A255: D255.2 J16.15 | length 485.2
  Bottom Layer w15: D255.2@11062.99,600.79 11220.47,600.79 11251.18,570.08 J16.15@11251.18,285.83
A256: D256.2 J16.16 | length 545.6
  Bottom Layer w15: J16.16@11251.18,185.83 11356.69,185.83 11417.32,246.46 D256.2@11417.32,600.79
B1: 
B2: 
B3: 
B4: 
B5: 
B6: 
B7: 
B8: 
B9: 
B10: 
B11: 
B12: 
B13: 
B14: 
B15: 
B16: 
B17: 
B18: 
B19: 
B20: 
B21: 
B22: 
B23: 
B24: 
B25: 
B26: 
B27: 
B28: 
B29: 
B30: 
B31: 
B32: 
B33: 
B34: 
B35: 
B36: 
B37: 
B38: 
B39: 
B40: 
B41: 
B42: 
B43: 
B44: 
B45: 
B46: 
B47: 
B48: 
B49: 
B50: 
B51: 
B52: 
B53: 
B54: 
B55: 
B56: 
B57: 
B58: 
B59: 
B60: 
B61: 
B62: 
B63: 
B64: 
B65: 
B66: 
B67: 
B68: 
B69: 
B70: 
B71: 
B72: 
B73: 
B74: 
B75: 
B76: 
B77: 
B78: 
B79: 
B80: 
B81: 
B82: 
B83: 
B84: 
B85: 
B86: 
B87: 
B88: 
B89: 
B90: 
B91: 
B92: 
B93: 
B94: 
B95: 
B96: 
B97: 
B98: 
B99: 
B100: 
B101: 
B102: 
B103: 
B104: 
B105: 
B106: 
B107: 
B108: 
B109: 
B110: 
B111: 
B112: 
B113: 
B114: 
B115: 
B116: 
B117: 
B118: 
B119: 
B120: 
B121: 
B122: 
B123: 
B124: 
B125: 
B126: 
B127: 
B128: 
B129: 
B130: 
B131: 
B132: 
B133: 
B134: 
B135: 
B136: 
B137: 
B138: 
B139: 
B140: 
B141: 
B142: 
B143: 
B144: 
B145: 
B146: 
B147: 
B148: 
B149: 
B150: 
B151: 
B152: 
B153: 
B154: 
B155: 
B156: 
B157: 
B158: 
B159: 
B160: 
B161: 
B162: 
B163: 
B164: 
B165: 
B166: 
B167: 
B168: 
B169: 
B170: 
B171: 
B172: 
B173: 
B174: 
B175: 
B176: 
B177: 
B178: 
B179: 
B180: 
B181: 
B182: 
B183: 
B184: 
B185: 
B186: 
B187: 
B188: 
B189: 
B190: 
B191: 
B192: 
B193: 
B194: 
B195: 
B196: 
B197: 
B198: 
B199: 
B200: 
B201: 
B202: 
B203: 
B204: 
B205: 
B206: 
B207: 
B208: 
B209: 
B210: 
B211: 
B212: 
B213: 
B214: 
B215: 
B216: 
B217: 
B218: 
B219: 
B220: 
B221: 
B222: 
B223: 
B224: 
B225: 
B226: 
B227: 
B228: 
B229: 
B230: 
B231: 
B232: 
B233: 
B234: 
B235: 
B236: 
B237: 
B238: 
B239: 
B240: 
C1: 
E1: 
E2: 
E3: 
E4: 
E5: 
E6: 
E7: 
E8: 
E9: 
E10: 
E11: 
E12: 
E13: 
E14: 
E15: 
E16: 
NetD1_2: 
NetD2_2: 
NetD3_2: 
NetD4_2: 
NetD5_2: 
NetD6_2: 
NetD7_2: 
NetD8_2: 
NetD9_2: 
NetD10_2: 
NetD11_2: 
NetD12_2: 
NetD13_2: 
NetD14_2: 
NetD15_2: 
NetD16_2: 
NetD17_2: 
NetD18_2: 
NetD19_2: 
NetD20_2: 
NetD21_2: 
NetD22_2: 
NetD23_2: 
NetD24_2: 
NetD25_2: 
NetD26_2: 
NetD27_2: 
NetD28_2: 
NetD29_2: 
NetD30_2: 
NetD31_2: 
NetD32_2: 
NetD33_2: 
NetD34_2: 
NetD35_2: 
NetD36_2: 
NetD37_2: 
NetD38_2: 
NetD39_2: 
NetD40_2: 
NetD41_2: 
NetD42_2: 
NetD43_2: 
NetD44_2: 
NetD45_2: 
NetD46_2: 
NetD47_2: 
NetD48_2: 
NetD49_2: 
NetD50_2: 
NetD51_2: 
NetD52_2: 
NetD53_2: 
NetD54_2: 
NetD55_2: 
NetD56_2: 
NetD57_2: 
NetD58_2: 
NetD59_2: 
NetD60_2: 
NetD61_2: 
NetD62_2: 
NetD63_2: 
NetD64_2: 
NetD65_2: 
NetD66_2: 
NetD67_2: 
NetD68_2: 
NetD69_2: 
NetD70_2: 
NetD71_2: 
NetD72_2: 
NetD73_2: 
NetD74_2: 
NetD75_2: 
NetD76_2: 
NetD77_2: 
NetD78_2: 
NetD79_2: 
NetD80_2: 
NetD81_2: 
NetD82_2: 
NetD83_2: 
NetD84_2: 
NetD85_2: 
NetD86_2: 
NetD87_2: 
NetD88_2: 
NetD89_2: 
NetD90_2: 
NetD91_2: 
NetD92_2: 
NetD93_2: 
NetD94_2: 
NetD95_2: 
NetD96_2: 
NetD97_2: 
NetD98_2: 
NetD99_2: 
NetD100_2: 
NetD101_2: 
NetD102_2: 
NetD103_2: 
NetD104_2: 
NetD105_2: 
NetD106_2: 
NetD107_2: 
NetD108_2: 
NetD109_2: 
NetD110_2: 
NetD111_2: 
NetD112_2: 
NetD113_2: 
NetD114_2: 
NetD115_2: 
NetD116_2: 
NetD117_2: 
NetD118_2: 
NetD119_2: 
NetD120_2: 
NetD121_2: 
NetD122_2: 
NetD123_2: 
NetD124_2: 
NetD125_2: 
NetD126_2: 
NetD127_2: 
NetD128_2: 
NetD129_2: 
NetD130_2: 
NetD131_2: 
NetD132_2: 
NetD133_2: 
NetD134_2: 
NetD135_2: 
NetD136_2: 
NetD137_2: 
NetD138_2: 
NetD139_2: 
NetD140_2: 
NetD141_2: 
NetD142_2: 
NetD143_2: 
NetD144_2: 
NetD145_2: 
NetD146_2: 
NetD147_2: 
NetD148_2: 
NetD149_2: 
NetD150_2: 
NetD151_2: 
NetD152_2: 
NetD153_2: 
NetD154_2: 
NetD155_2: 
NetD156_2: 
NetD157_2: 
NetD158_2: 
NetD159_2: 
NetD160_2: 
NetD161_2: 
NetD162_2: 
NetD163_2: 
NetD164_2: 
NetD165_2: 
NetD166_2: 
NetD167_2: 
NetD168_2: 
NetD169_2: 
NetD170_2: 
NetD171_2: 
NetD172_2: 
NetD173_2: 
NetD174_2: 
NetD175_2: 
NetD176_2: 
NetD177_2: 
NetD178_2: 
NetD179_2: 
NetD180_2: 
NetD181_2: 
NetD182_2: 
NetD183_2: 
NetD184_2: 
NetD185_2: 
NetD186_2: 
NetD187_2: 
NetD188_2: 
NetD189_2: 
NetD190_2: 
NetD191_2: 
NetD192_2: 
NetD193_2: 
NetD194_2: 
NetD195_2: 
NetD196_2: 
NetD197_2: 
NetD198_2: 
NetD199_2: 
NetD200_2: 
NetD201_2: 
NetD202_2: 
NetD203_2: 
NetD204_2: 
NetD205_2: 
NetD206_2: 
NetD207_2: 
NetD208_2: 
NetD209_2: 
NetD210_2: 
NetD211_2: 
NetD212_2: 
NetD213_2: 
NetD214_2: 
NetD215_2: 
NetD216_2: 
NetD217_2: 
NetD218_2: 
NetD219_2: 
NetD220_2: 
NetD221_2: 
NetD222_2: 
NetD223_2: 
NetD224_2: 
NetD225_2: 
NetD226_2: 
NetD227_2: 
NetD228_2: 
NetD229_2: 
NetD230_2: 
NetD231_2: 
NetD232_2: 
NetD233_2: 
NetD234_2: 
NetD235_2: 
NetD236_2: 
NetD237_2: 
NetD238_2: 
NetD239_2: 
NetD240_2: 
NetD241_2: 
NetD242_2: 
NetD243_2: 
NetD244_2: 
NetD245_2: 
NetD246_2: 
NetD247_2: 
NetD248_2: 
NetD249_2: 
NetD250_2: 
NetD251_2: 
NetD252_2: 
NetD253_2: 
NetD254_2: 
NetD255_2: 
NetD256_2: 
SCL13: 
SCL14: 
SCL15: 
SCL16: 
SDA13: 
SDA14: 
SDA15: 
SDA16: 

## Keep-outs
Keep-Out Layer:
  lines w10: 0,0 0,3622.05 11850.39,3622.05 11850.39,0 0,0

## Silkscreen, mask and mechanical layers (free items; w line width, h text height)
Mechanical 1:
  lines w10: 0,0 11850.39,0 11850.39,3622.05 0,3622.05 0,0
